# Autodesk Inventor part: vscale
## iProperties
Created: 2007-02
Part Number: vscale
Document SubType Name: Modeling
Designer: John Blackburn
Author: John Blackburn
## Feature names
1. Extrusion1
2. Fillet1
